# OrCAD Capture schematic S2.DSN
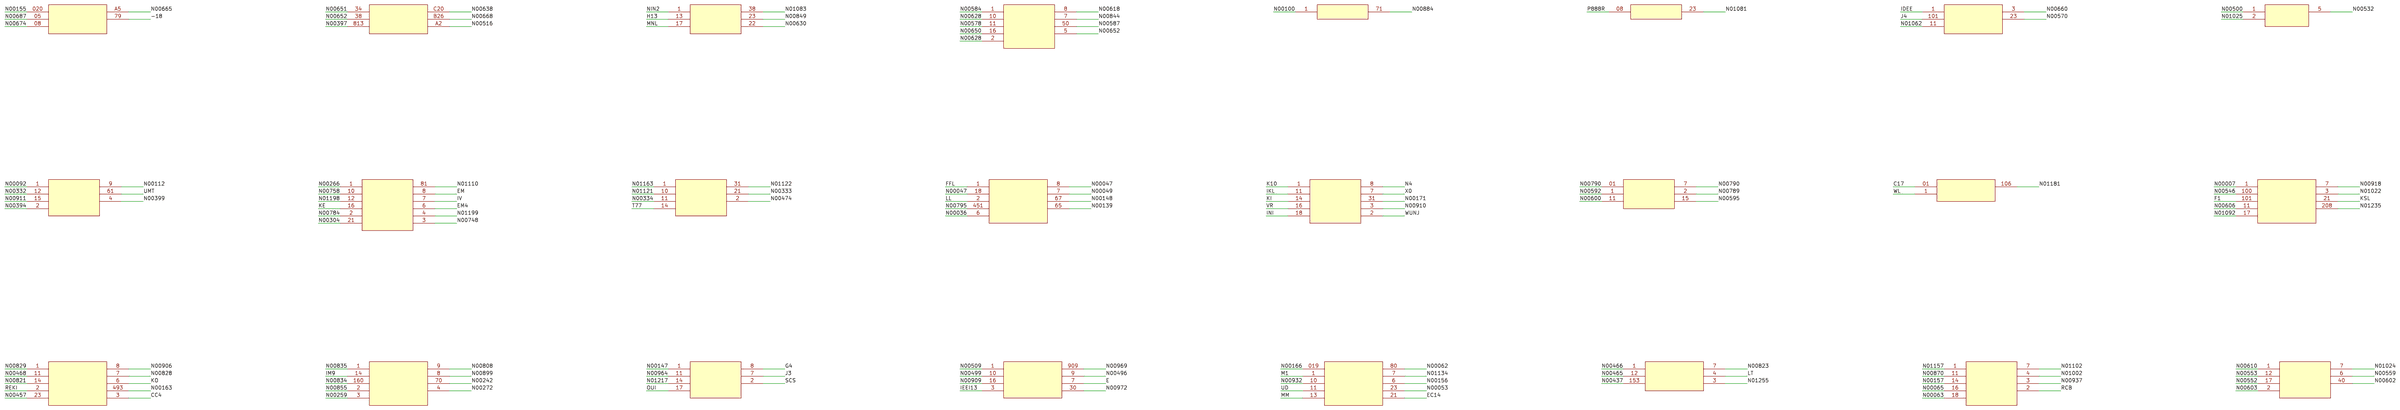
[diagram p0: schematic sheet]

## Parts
P1  CONNECTOR
P2  CONNECTOR
U6  1R
U7  74F374
U8  TC514100
U43  74F374
U53  UNKNOWN
U67  UNKNOWN
U70  74F244
U74  TC514100
U76  UNKNOWN
U94  TC514100
U_1  TC514100
U_2  TC514100
U_3  TC514100
U_4  TC514100
U_5  74F211
U_6  TC514100
U_7  74F374
U_8  TC514100
U_9  74F374
U_10  74F273
U_11  74F244
U_12  74F374

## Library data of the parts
P1 = OBS_P1
P2 = OBS_P2
U6 = OBS_U6
U7 = OBS_U7
U8 = OBS_U8
U43 = OBS_U43
U53 = OBS_U53
U67 = OBS_U67
U70 = OBS_U70
U74 = OBS_U74
U76 = OBS_U76
U94 = OBS_U94
U_1 = OBS_U_1
U_2 = OBS_U_2
U_3 = OBS_U_3
U_4 = OBS_U_4
U_5 = OBS_U_5
U_6 = OBS_U_6
U_7 = OBS_U_7
U_8 = OBS_U_8
U_9 = OBS_U_9
U_10 = OBS_U_10
U_11 = OBS_U_11
U_12 = OBS_U_12

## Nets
-18: P1.79
C17: U_11.01
CC4: U_2.3
E: U_5.7
EC14: U_6.21
EM: U76.8
EM4: U76.6
F1: U_12.101
FFL: U94.1
G4: U_4.8
H13: U43.13
IDEE: U7.1
IEEI13: U_5.3
IKL: U_1.11
IM9: U_3.14
INI: U_1.18
IV: U76.7
J3: U_4.7
J4: U7.101
K10: U_1.1
KE: U76.16
KI: U_1.14
KO: U_2.6
KSL: U_12.21
LL: U94.2
LT: U_7.4
M1: U_6.1
MM: U_6.13
MNL: U43.17
N4: U_1.8
NIN2: U43.1
OUI: U_4.17
P888R: U67.08
RCB: U_8.2
REKI: U_2.2
SCS: U_4.2
T77: U8.14
UD: U_6.11
UMT: U74.61
VR: U_1.16
WL: U_11.1
WUNJ: U_1.2
X0: U_1.7
N00047: U94.8 U94.18
N00628: U53.2 U53.10
N00652: P2.38 U53.5
N00790: U_10.01 U_10.7

Not connected (* = marked no-connect by the designer): P1 05 08 020 A5; P2 34 813 A2 B26 C20; U6 1 71; U7 3 11 23; U8 1 2 10 11 21 31; U43 22 23 38; U53 1 7 8 11 16 50; U67 23; U70 1 2 5; U74 1 2 4 9 12 15; U76 1 2 3 4 10 12 21 81; U94 6 7 65 67 451; U_1 3 31; U_2 1 7 8 11 14 23 493; U_3 1 2 3 4 8 9 70 160; U_4 1 11 14; U_5 1 9 10 16 30 909; U_6 6 7 10 019 23 80; U_7 1 3 7 12 153; U_8 1 3 4 7 11 14 16 18; U_9 1 2 6 7 12 17 40; U_10 1 2 11 15; U_11 106; U_12 1 3 7 11 17 100 208
